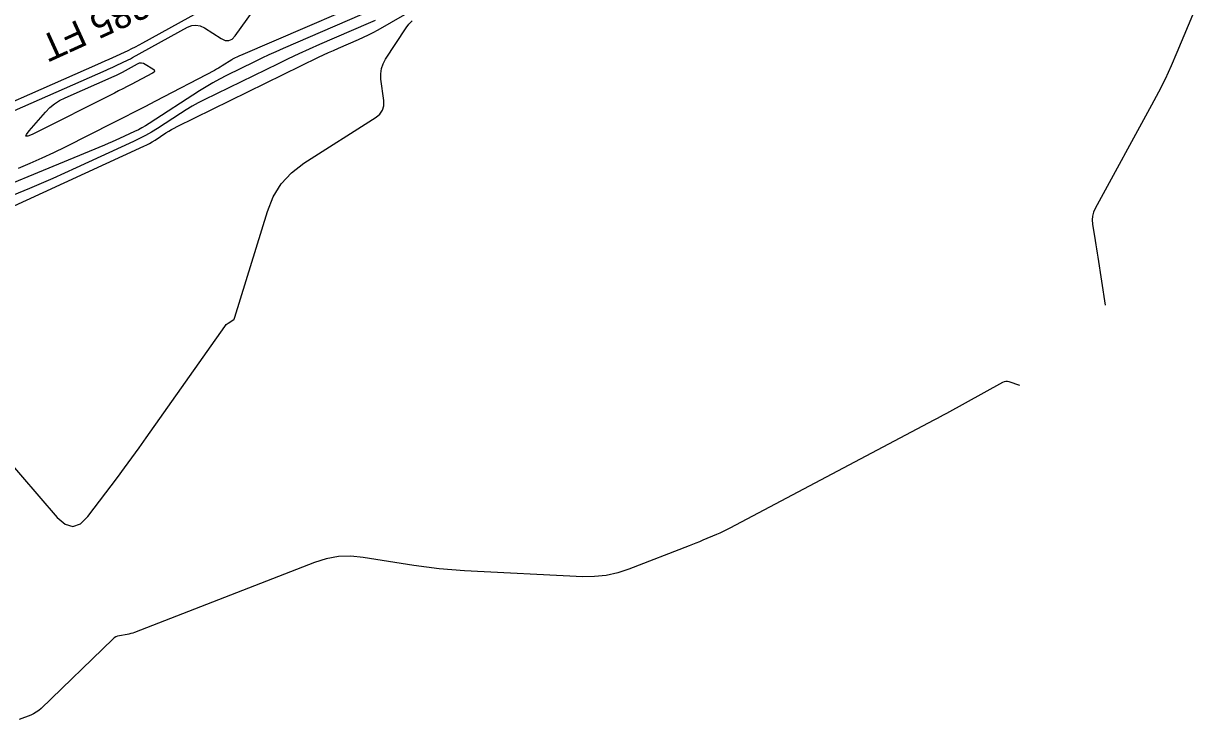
# Model space of a CAD drawing. Extents: x 1768942 to 1774819, y 723037 to 732099.
# Drawn here: x 1771237.8 to 1771498.3, y 724787.9 to 724942 of the extents above; entities that cross this region are included whole.
import ezdxf

# ---------------------------------------------------------------- set-up
doc = ezdxf.new("R2010")
doc.units = 0
doc.layers.add('R_Contour Annot', color=7, linetype='Continuous')
doc.layers.add('R_Contours', color=7, linetype='Continuous')

msp = doc.modelspace()

# ---------------------------------------------------------------- linework, layer by layer
at = {"layer": 'R_Contours'}
for points in [[(1771322.25, 724950.7), (1771285.85, 724934.97), (1771285.69, 724934.9), (1771285.53, 724934.83), (1771285.37, 724934.76), (1771285.21, 724934.68), (1771284.57, 724934.37), (1771284.42, 724934.29), (1771284.26, 724934.2), (1771284.11, 724934.11), (1771283.96, 724934.02), (1771281.82, 724932.63), (1771281.41, 724932.37), (1771281, 724932.12), (1771280.58, 724931.89), (1771280.15, 724931.66), (1771267.03, 724924.82), (1771264.7, 724923.61), (1771262.36, 724922.41), (1771260.02, 724921.21), (1771257.68, 724920.03), (1771247.03, 724914.66), (1771244.46, 724913.4), (1771241.87, 724912.18), (1771239.26, 724911.01), (1771236.63, 724909.9)], [(1771233.86, 724900.76), (1771264.46, 724914.84), (1771265.11, 724915.15), (1771265.74, 724915.49), (1771266.36, 724915.84), (1771266.97, 724916.22), (1771269.38, 724917.79), (1771269.98, 724918.17), (1771270.6, 724918.53), (1771271.23, 724918.88), (1771271.87, 724919.2), (1771303.17, 724934.55), (1771304.26, 724935.07), (1771305.36, 724935.59), (1771306.46, 724936.09), (1771307.57, 724936.57), (1771312.02, 724938.49), (1771313.12, 724938.99), (1771314.21, 724939.52), (1771315.28, 724940.07), (1771316.34, 724940.66), (1771328.7, 724947.8)], [(1771498.27, 724947.64), (1771493.29, 724935.64), (1771492.01, 724932.66), (1771490.64, 724929.72), (1771489.2, 724926.82), (1771487.68, 724923.95), (1771475.16, 724901.08), (1771474.79, 724900.25), (1771474.57, 724899.4), (1771474.5, 724898.52), (1771474.58, 724897.61), (1771475.2, 724893.95), (1771475.35, 724893.03), (1771475.5, 724892.12), (1771475.64, 724891.2), (1771475.78, 724890.28), (1771477.35, 724879.69)], [(1771213.63, 724913.04), (1771256.1, 724931.7), (1771256.6, 724931.92), (1771257.1, 724932.14), (1771257.59, 724932.37), (1771258.09, 724932.6), (1771260.06, 724933.52), (1771260.55, 724933.75), (1771261.04, 724933.99), (1771261.52, 724934.24), (1771262, 724934.5), (1771274.12, 724941.19), (1771275.08, 724941.59), (1771276.03, 724941.7), (1771276.97, 724941.52), (1771277.9, 724941.07), (1771281.6, 724938.7), (1771282.49, 724938.3), (1771283.31, 724938.26), (1771284.05, 724938.6), (1771284.73, 724939.31), (1771288.68, 724944.87)], [(1771318.2, 724946.36), (1771295.31, 724936.47), (1771293.73, 724935.77), (1771292.15, 724935.06), (1771290.58, 724934.32), (1771289.02, 724933.57), (1771282.81, 724930.52), (1771281.27, 724929.74), (1771279.75, 724928.91), (1771278.26, 724928.03), (1771276.79, 724927.11), (1771265.63, 724919.86), (1771264.86, 724919.37), (1771264.06, 724918.92), (1771263.26, 724918.49), (1771262.44, 724918.1), (1771259.11, 724916.57), (1771258.28, 724916.19), (1771257.44, 724915.82), (1771256.61, 724915.46), (1771255.76, 724915.1), (1771219.63, 724900.16)], [(1771219.71, 724917.82), (1771254.27, 724933), (1771255.11, 724933.37), (1771255.95, 724933.75), (1771256.79, 724934.13), (1771257.63, 724934.52), (1771260.98, 724936.09), (1771261.81, 724936.48), (1771262.64, 724936.9), (1771263.46, 724937.32), (1771264.27, 724937.76), (1771278.6, 724945.67)], [(1771315.7, 724942.71), (1771314.14, 724942.01), (1771303.37, 724937.35), (1771301.06, 724936.34), (1771298.77, 724935.3), (1771296.48, 724934.23), (1771294.21, 724933.13), (1771277.87, 724925.12), (1771276.52, 724924.43), (1771275.18, 724923.7), (1771273.87, 724922.93), (1771272.59, 724922.13), (1771267.48, 724918.81), (1771266.19, 724918), (1771264.88, 724917.25), (1771263.54, 724916.54), (1771262.17, 724915.88), (1771249.5, 724910.05), (1771246.92, 724908.88), (1771244.33, 724907.73), (1771241.73, 724906.61), (1771239.12, 724905.52), (1771221.15, 724898.09)], [(1771233.08, 724846.84), (1771245.28, 724832.65), (1771247.03, 724831.12), (1771248.75, 724830.65), (1771250.43, 724831.23), (1771252.08, 724832.86), (1771258.61, 724841.5), (1771260.23, 724843.66), (1771261.84, 724845.84), (1771263.42, 724848.04), (1771264.99, 724850.24), (1771282.4, 724874.94), (1771282.56, 724875.15), (1771282.74, 724875.34), (1771282.93, 724875.51), (1771283.14, 724875.66), (1771284.39, 724876.45), (1771284.43, 724876.48), (1771284.46, 724876.51), (1771284.49, 724876.55), (1771284.5, 724876.59), (1771284.56, 724876.78), (1771284.58, 724876.83), (1771284.59, 724876.88), (1771284.61, 724876.92), (1771284.62, 724876.97), (1771291.83, 724900.43), (1771293.12, 724903.65), (1771294.9, 724906.5), (1771297.17, 724908.97), (1771299.92, 724911.07), (1771315.9, 724921.26), (1771316.77, 724921.98), (1771317.35, 724922.83), (1771317.63, 724923.82), (1771317.62, 724924.95), (1771317, 724929.74), (1771316.94, 724930.91), (1771317.1, 724932.04), (1771317.45, 724933.12), (1771318.02, 724934.15), (1771322.6, 724941.08), (1771323.2, 724941.88), (1771323.87, 724942.59)], [(1771458.51, 724861.85), (1771456.14, 724862.66), (1771455.75, 724862.76), (1771455.36, 724862.77), (1771454.99, 724862.69), (1771454.62, 724862.53), (1771442.23, 724855.68), (1771441.54, 724855.3), (1771440.85, 724854.92), (1771440.16, 724854.55), (1771439.47, 724854.18), (1771394.27, 724830.24), (1771393.54, 724829.87), (1771392.8, 724829.51), (1771392.06, 724829.17), (1771391.3, 724828.84), (1771388.27, 724827.58), (1771387.51, 724827.27), (1771386.75, 724826.96), (1771385.99, 724826.66), (1771385.22, 724826.36), (1771371.91, 724821.18), (1771369.42, 724820.36), (1771366.88, 724819.8), (1771364.29, 724819.53), (1771361.67, 724819.52), (1771335.48, 724820.85), (1771332.66, 724821.03), (1771329.85, 724821.28), (1771327.05, 724821.62), (1771324.25, 724822.02), (1771313.09, 724823.8), (1771310.32, 724824.06), (1771307.58, 724823.96), (1771304.89, 724823.48), (1771302.24, 724822.64), (1771262.42, 724807.18), (1771262.01, 724807.03), (1771261.61, 724806.91), (1771261.19, 724806.81), (1771260.77, 724806.72), (1771259.08, 724806.44), (1771258.68, 724806.34), (1771258.3, 724806.18), (1771257.94, 724805.97), (1771257.62, 724805.7), (1771241.71, 724790.33), (1771241.19, 724789.89), (1771240.65, 724789.49), (1771240.06, 724789.16), (1771239.44, 724788.89), (1771236.88, 724787.9)]]:
    msp.add_lwpolyline(points, dxfattribs=at)
msp.add_lwpolyline([(1771263.54, 724933.29), (1771263.96, 724933.34), (1771264.38, 724933.26), (1771264.8, 724933.06), (1771266.46, 724932), (1771266.77, 724931.74), (1771266.86, 724931.49), (1771266.75, 724931.24), (1771266.41, 724931.01), (1771261.7, 724928.56), (1771260.77, 724928.07), (1771259.83, 724927.59), (1771258.9, 724927.11), (1771257.96, 724926.64), (1771239.75, 724917.46), (1771238.79, 724917.05), (1771238.37, 724917.05), (1771238.47, 724917.47), (1771239.11, 724918.3), (1771242.71, 724922.43), (1771243.65, 724923.41), (1771244.69, 724924.26), (1771245.81, 724924.99), (1771247.02, 724925.6), (1771257.94, 724930.4), (1771258.09, 724930.46), (1771258.24, 724930.53), (1771258.39, 724930.6), (1771258.54, 724930.67), (1771259.14, 724930.95), (1771259.29, 724931.02), (1771259.43, 724931.09), (1771259.58, 724931.17), (1771259.72, 724931.25), (1771263.11, 724933.11)], close=True, dxfattribs=at)

# ---------------------------------------------------------------- texts
at = {"layer": 'R_Contour Annot'}
msp.add_text('285 FT', height=6, rotation=204.4751, dxfattribs=at).set_placement((1771264.1, 724949.45))

doc.saveas('drawing.dxf')
